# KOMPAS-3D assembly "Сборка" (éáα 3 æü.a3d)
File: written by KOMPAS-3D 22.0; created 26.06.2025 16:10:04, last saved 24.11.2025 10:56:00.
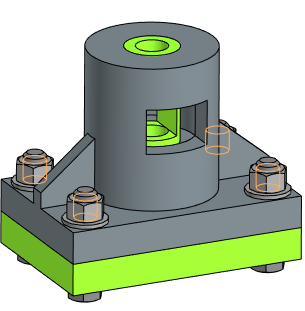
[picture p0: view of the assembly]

Document properties: Автор: Helen; Полное имя файла: C:\Для ноута\Инженерная графика\ППЭ 2025-2026\Варианты 1-38\Вариант 3 СБ\Вар 3 СБ\Вар 3 СБ.a3d

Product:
- Component [detail]: Основание  | designation Вариант 3  | qty 1  | Масса: 2.63815; source file: Основание вар 3.m3d
- Component [detail]: Nodes  | qty 1  | Масса: 4.469151; source file: Корпус вар3.m3d
- Component [detail]: Болт М14x60 ГОСТ 15591-70  | qty 4  | Масса: 0.091885; source file: Болт М14x60 ГОСТ 15591-70.m3d
- Component [detail]: Сборка  | qty 4  | Масса: 0.008612; source file: Шайба 14.m3d
- Component [detail]: Сборка  | qty 4  | Масса: 0.02533; source file: Гайка М14.m3d
- Part/product: Сборка
    Масса: 7.610607

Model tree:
1. Массив по сетке:1  (with: Операция без истории:1, Элемент выдавливания:3, Элемент выдавливания:1)  (labels: Фаска:3)  (4 pattern instances)
     Шаг 1 = 120; Угол раствора = 90; Шаг 2 = 70

Referenced files in C:\Для ноута\Инженерная графика\ППЭ 2025-2026\Варианты 1-38\Вариант 3 СБ\Вар 3 СБ\: Основание вар 3.m3d, Корпус вар3.m3d
Referenced files in D:\MY\WORK\MPEI\ППЭ_2025-2026\Варианты\Вар 2 СБ\: Болт М14x60 ГОСТ 15591-70.m3d, Шайба 14.m3d, Гайка М14.m3d
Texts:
  Вариант 3 Основание
  Болт М14x60 ГОСТ 15591-70 (1)
  Сборка (1)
